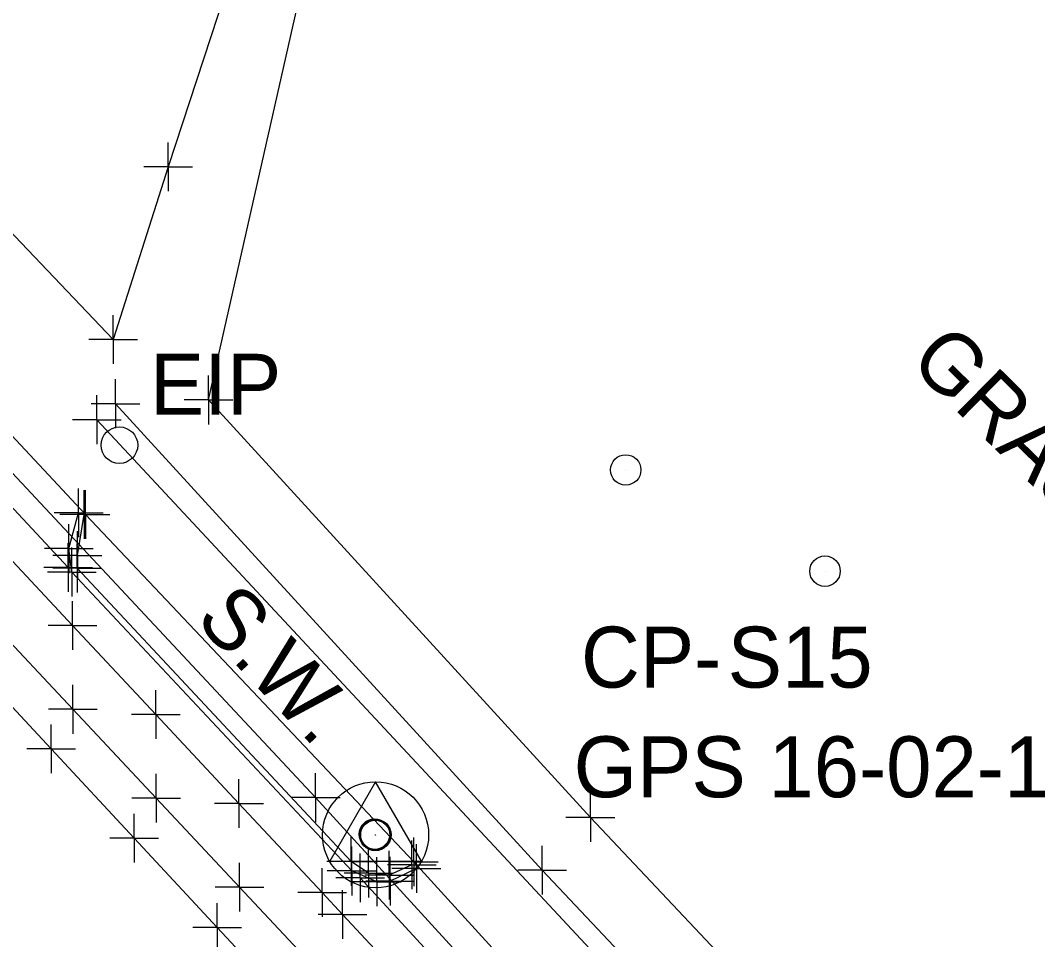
# Model space of a CAD drawing. Extents: x 0 to 1944463, y 0 to 420651.
# Drawn here: x 1943638.6 to 1943722, y 417032.9 to 417108.3 of the extents above; entities that cross this region are included whole.
import ezdxf

# ---------------------------------------------------------------- set-up
doc = ezdxf.new("R2010")
doc.units = 0
for name, color, linetype in [('SUR - CTRL - Points - Numbers', 7, 'Continuous'), ('SUR - CTRL - Points Text', 7, 'Continuous'), ('SUR - DTM - Breaklines', 7, 'Continuous'), ('SUR - DTM - Breaklines - Points - Locators', 7, 'Continuous'), ('SUR - DTM - Spot Points - Locators', 7, 'Continuous'), ('SUR - PROPERTY - Property Lines', 7, 'Continuous'), ('SUR - PROPERTY - Property Markers', 7, 'Continuous'), ('SUR - PROPERTY - ROW Lines', 7, 'Continuous'), ('SUR - TR-CTRL - Pavement Marking', 7, 'Continuous'), ('SUR - TR-CTRL - Pavement Marking - Points - Locators', 7, 'Continuous'), ('SUR - TRAN - Features', 7, 'Continuous'), ('SUR - TRAN - Features - Points - Locators', 7, 'Continuous'), ('SUR - TRAN - Features Text', 7, 'Continuous'), ('SUR - TRAN - Roads', 7, 'Continuous'), ('SUR - UTL - Water', 7, 'Continuous'), ('SUR - UTL - Water - Points - Locators', 7, 'Continuous'), ('SUR - UTL - Water Text', 7, 'Continuous'), ('SUR - VEG - Features Text', 7, 'Continuous'), ('TopoDOT_Transients', 7, 'Continuous')]:
    doc.layers.add(name, color=color, linetype=linetype)

msp = doc.modelspace()

# ---------------------------------------------------------------- linework, layer by layer
at = {"layer": 'SUR - DTM - Breaklines'}
for points in [[(1943783.807, 417052.199), (1943780.542, 417004.601), (1943779.213, 416989.031), (1943776.981, 416981.358), (1943762.371, 416972.888), (1943751.859, 416974.896), (1943741.512, 416982.766), (1943718.161, 417008.084), (1943685.342, 417042.903), (1943654.02, 417077.164), (1943664.758, 417124.782), (1943668.661, 417143.414)], [(1943733.578, 416981.529), (1943714.058, 417003.915), (1943681.394, 417038.588), (1943646.389, 417076.862)], [(1943670.69, 417039.025), (1943668.832, 417038.166), (1943667.154, 417038.334), (1943665.717, 417039.279), (1943643.234, 417063.364), (1943643.254, 417064.4), (1943643.818, 417067.761)], [(1943683.48, 417019.426), (1943666.457, 417037.948)]]:
    msp.add_lwpolyline(points, dxfattribs=at)
at = {"layer": 'SUR - DTM - Breaklines - Points - Locators'}
for p, q in [((1943646.389, 417076.862), (1943646.389, 417078.862)), ((1943654.02, 417077.164), (1943654.02, 417079.164)), ((1943646.389, 417076.862), (1943644.389, 417076.862)), ((1943646.389, 417076.862), (1943648.389, 417076.862)), ((1943646.389, 417076.862), (1943646.389, 417074.862)), ((1943654.02, 417077.164), (1943652.02, 417077.164)), ((1943654.02, 417077.164), (1943656.02, 417077.164)), ((1943654.02, 417077.164), (1943654.02, 417075.164)), ((1943643.818, 417067.761), (1943643.818, 417069.761)), ((1943643.818, 417067.761), (1943641.818, 417067.761)), ((1943643.818, 417067.761), (1943645.818, 417067.761)), ((1943643.818, 417067.761), (1943643.818, 417065.761)), ((1943643.254, 417064.4), (1943643.254, 417066.4)), ((1943643.234, 417063.364), (1943643.234, 417065.364)), ((1943643.254, 417064.4), (1943641.254, 417064.4)), ((1943643.254, 417064.4), (1943645.254, 417064.4)), ((1943643.254, 417064.4), (1943643.254, 417062.4)), ((1943643.234, 417063.364), (1943641.234, 417063.364)), ((1943643.234, 417063.364), (1943645.234, 417063.364)), ((1943643.234, 417063.364), (1943643.234, 417061.364)), ((1943685.342, 417042.903), (1943685.342, 417044.903)), ((1943685.342, 417042.903), (1943683.342, 417042.903)), ((1943685.342, 417042.903), (1943687.342, 417042.903)), ((1943685.342, 417042.903), (1943685.342, 417040.903)), ((1943665.717, 417039.279), (1943665.717, 417041.279)), ((1943670.69, 417039.025), (1943670.69, 417041.025)), ((1943667.154, 417038.334), (1943667.154, 417040.334)), ((1943668.832, 417038.166), (1943668.832, 417040.166)), ((1943681.394, 417038.588), (1943681.394, 417040.588)), ((1943665.717, 417039.279), (1943663.717, 417039.279)), ((1943665.717, 417039.279), (1943667.717, 417039.279)), ((1943665.717, 417039.279), (1943665.717, 417037.279)), ((1943666.457, 417037.948), (1943666.457, 417039.948)), ((1943670.69, 417039.025), (1943668.69, 417039.025)), ((1943670.69, 417039.025), (1943672.69, 417039.025)), ((1943670.69, 417039.025), (1943670.69, 417037.025)), ((1943681.394, 417038.588), (1943679.394, 417038.588)), ((1943681.394, 417038.588), (1943683.394, 417038.588)), ((1943681.394, 417038.588), (1943681.394, 417036.588)), ((1943666.457, 417037.948), (1943664.457, 417037.948)), ((1943667.154, 417038.334), (1943665.154, 417038.334)), ((1943666.457, 417037.948), (1943668.457, 417037.948)), ((1943666.457, 417037.948), (1943666.457, 417035.948)), ((1943668.832, 417038.166), (1943666.832, 417038.166)), ((1943667.154, 417038.334), (1943669.154, 417038.334)), ((1943667.154, 417038.334), (1943667.154, 417036.334)), ((1943668.832, 417038.166), (1943670.832, 417038.166)), ((1943668.832, 417038.166), (1943668.832, 417036.166))]:
    msp.add_line(p, q, dxfattribs=at)
at = {"layer": 'SUR - DTM - Spot Points - Locators'}
for p, q in [((1943688.254, 417071.412), (1943688.254, 417071.412)), ((1943704.603, 417063.108), (1943704.603, 417063.108))]:
    msp.add_line(p, q, dxfattribs=at)
for centre in [(1943688.243, 417071.422), (1943704.592, 417063.118)]:
    msp.add_circle(centre, 1.25, dxfattribs=at)
at = {"layer": 'SUR - PROPERTY - Property Lines'}
for p, q in [((1943642.86, 417058.655), (1943642.86, 417060.655)), ((1943642.86, 417058.655), (1943640.86, 417058.655)), ((1943642.86, 417058.655), (1943644.86, 417058.655)), ((1943642.86, 417058.655), (1943642.86, 417056.655)), ((1943649.687, 417051.348), (1943649.687, 417053.348)), ((1943649.687, 417051.348), (1943647.687, 417051.348)), ((1943649.687, 417051.348), (1943651.687, 417051.348)), ((1943649.687, 417051.348), (1943649.687, 417049.348)), ((1943656.515, 417044.042), (1943656.515, 417046.042)), ((1943656.515, 417044.042), (1943654.515, 417044.042)), ((1943656.515, 417044.042), (1943658.515, 417044.042)), ((1943656.515, 417044.042), (1943656.515, 417042.042)), ((1943663.342, 417036.735), (1943663.342, 417038.735)), ((1943665.012, 417034.948), (1943665.012, 417036.948)), ((1943663.342, 417036.735), (1943661.342, 417036.735)), ((1943663.342, 417036.735), (1943665.342, 417036.735)), ((1943663.342, 417036.735), (1943663.342, 417034.735)), ((1943665.012, 417034.948), (1943663.012, 417034.948)), ((1943665.012, 417034.948), (1943667.012, 417034.948)), ((1943665.012, 417034.948), (1943665.012, 417032.948))]:
    msp.add_line(p, q, dxfattribs=at)
at = {"layer": 'SUR - PROPERTY - Property Markers'}
msp.add_circle((1943646.708, 417073.456), 1.5, dxfattribs=at)
at = {"layer": 'SUR - PROPERTY - ROW Lines'}
for p, q in [((1943667.644, 417041.522), (1943667.644, 417041.522)), ((1943667.663, 417041.437), (1943667.663, 417041.437)), ((1943667.664, 417041.484), (1943667.664, 417041.484)), ((1943667.665, 417041.462), (1943667.665, 417041.462)), ((1943667.668, 417041.477), (1943667.668, 417041.477)), ((1943667.669, 417041.488), (1943667.669, 417041.488)), ((1943667.671, 417041.463), (1943667.671, 417041.463)), ((1943667.678, 417041.51), (1943667.678, 417041.51)), ((1943667.68, 417041.437), (1943667.68, 417041.437)), ((1943667.699, 417041.466), (1943667.699, 417041.466)), ((1943667.702, 417041.439), (1943667.702, 417041.439)), ((1943667.703, 417041.473), (1943667.703, 417041.473)), ((1943667.704, 417041.421), (1943667.704, 417041.421)), ((1943667.705, 417041.485), (1943667.705, 417041.485)), ((1943667.706, 417041.418), (1943667.706, 417041.418)), ((1943667.708, 417041.451), (1943667.708, 417041.451)), ((1943667.709, 417041.479), (1943667.709, 417041.479)), ((1943667.712, 417041.474), (1943667.712, 417041.474)), ((1943667.713, 417041.446), (1943667.713, 417041.446)), ((1943667.717, 417041.449), (1943667.717, 417041.449)), ((1943667.72, 417041.432), (1943667.72, 417041.432)), ((1943667.723, 417041.439), (1943667.723, 417041.439)), ((1943667.725, 417041.493), (1943667.725, 417041.493)), ((1943667.73, 417041.497), (1943667.73, 417041.497)), ((1943667.731, 417041.428), (1943667.731, 417041.428)), ((1943667.738, 417041.439), (1943667.738, 417041.439)), ((1943667.739, 417041.502), (1943667.739, 417041.502)), ((1943667.76, 417041.463), (1943667.76, 417041.463))]:
    msp.add_line(p, q, dxfattribs=at)
for centre in [(1943667.633, 417041.533), (1943667.652, 417041.448), (1943667.653, 417041.495), (1943667.655, 417041.472), (1943667.657, 417041.487), (1943667.658, 417041.498), (1943667.66, 417041.473), (1943667.667, 417041.521), (1943667.669, 417041.448), (1943667.688, 417041.477), (1943667.691, 417041.449), (1943667.693, 417041.484), (1943667.694, 417041.495), (1943667.693, 417041.432), (1943667.696, 417041.429), (1943667.697, 417041.462), (1943667.699, 417041.489), (1943667.701, 417041.484), (1943667.702, 417041.457), (1943667.707, 417041.459), (1943667.71, 417041.443), (1943667.712, 417041.45), (1943667.714, 417041.504), (1943667.719, 417041.508), (1943667.72, 417041.439), (1943667.727, 417041.45), (1943667.728, 417041.513), (1943667.749, 417041.473)]:
    msp.add_circle(centre, 1.25, dxfattribs=at)
at = {"layer": 'SUR - TR-CTRL - Pavement Marking'}
msp.add_lwpolyline([(1943581.298, 417112.609), (1943588.124, 417105.301), (1943594.95, 417097.993), (1943601.776, 417090.685), (1943608.602, 417083.377), (1943615.428, 417076.07), (1943622.255, 417068.762), (1943627.48, 417063.167), (1943634.292, 417055.846), (1943641.104, 417048.525), (1943647.916, 417041.204), (1943654.727, 417033.882), (1943661.539, 417026.561), (1943668.351, 417019.24), (1943675.163, 417011.919), (1943681.975, 417004.598), (1943688.786, 416997.277), (1943695.598, 416989.955), (1943702.41, 416982.634), (1943709.222, 416975.313), (1943716.033, 416967.992), (1943716.328, 416967.675)], dxfattribs=at)
at = {"layer": 'SUR - TR-CTRL - Pavement Marking - Points - Locators'}
for p, q in [((1943641.104, 417048.525), (1943641.104, 417050.525)), ((1943641.104, 417048.525), (1943639.104, 417048.525)), ((1943641.104, 417048.525), (1943643.104, 417048.525)), ((1943641.104, 417048.525), (1943641.104, 417046.525)), ((1943647.916, 417041.204), (1943647.916, 417043.204)), ((1943647.916, 417041.204), (1943645.916, 417041.204)), ((1943647.916, 417041.204), (1943649.916, 417041.204)), ((1943647.916, 417041.204), (1943647.916, 417039.204)), ((1943654.727, 417033.882), (1943654.727, 417035.882)), ((1943654.727, 417033.882), (1943652.727, 417033.882)), ((1943654.727, 417033.882), (1943656.727, 417033.882)), ((1943654.727, 417033.882), (1943654.727, 417031.882))]:
    msp.add_line(p, q, dxfattribs=at)
at = {"layer": 'SUR - TRAN - Features'}
for p, q in [((1943626.355, 417086.597), (1943643.925, 417067.757)), ((1943670.848, 417039.258), (1943685.046, 417023.729))]:
    msp.add_line(p, q, dxfattribs=at)
for points in [[(1943675.686, 417174.052), (1943662.302, 417131.665), (1943650.711, 417096.292), (1943646.198, 417082.119), (1943613.312, 417116.676)], [(1943587.024, 417111.249), (1943593.873, 417103.962), (1943600.721, 417096.675), (1943607.569, 417089.388), (1943614.417, 417082.101), (1943621.266, 417074.814), (1943628.114, 417067.527), (1943634.962, 417060.24), (1943636.052, 417059.081), (1943642.884, 417051.779), (1943649.716, 417044.477), (1943656.548, 417037.174), (1943663.381, 417029.872), (1943670.213, 417022.57), (1943677.045, 417015.268), (1943683.877, 417007.966), (1943690.71, 417000.664), (1943697.09, 416993.845), (1943703.922, 416986.543), (1943710.755, 416979.241), (1943717.587, 416971.939), (1943719.511, 416969.883)], [(1943642.497, 417063.413), (1943623.163, 417084.153)], [(1943738.63, 416975.053), (1943710.045, 417005.565), (1943644.857, 417075.549)], [(1943671.068, 417038.711), (1943668.914, 417037.685), (1943667.817, 417037.632), (1943665.763, 417038.512), (1943642.793, 417063.045), (1943642.558, 417064.965), (1943643.362, 417067.907)], [(1943670.848, 417039.258), (1943643.925, 417067.757)]]:
    msp.add_lwpolyline(points, dxfattribs=at)
at = {"layer": 'SUR - TRAN - Features - Points - Locators'}
for p, q in [((1943650.711, 417096.292), (1943650.711, 417098.292)), ((1943650.711, 417096.292), (1943648.711, 417096.292)), ((1943650.711, 417096.292), (1943652.711, 417096.292)), ((1943650.711, 417096.292), (1943650.711, 417094.292)), ((1943646.198, 417082.119), (1943646.198, 417084.119)), ((1943646.198, 417082.119), (1943644.198, 417082.119)), ((1943646.198, 417082.119), (1943648.198, 417082.119)), ((1943646.198, 417082.119), (1943646.198, 417080.119)), ((1943644.857, 417075.549), (1943644.857, 417077.549)), ((1943644.857, 417075.549), (1943642.857, 417075.549)), ((1943644.857, 417075.549), (1943646.857, 417075.549)), ((1943644.857, 417075.549), (1943644.857, 417073.549)), ((1943643.362, 417067.907), (1943643.362, 417069.907)), ((1943643.925, 417067.757), (1943643.925, 417069.757)), ((1943643.362, 417067.907), (1943641.362, 417067.907)), ((1943643.925, 417067.757), (1943641.925, 417067.757)), ((1943643.362, 417067.907), (1943645.362, 417067.907)), ((1943643.362, 417067.907), (1943643.362, 417065.907)), ((1943643.925, 417067.757), (1943645.925, 417067.757)), ((1943643.925, 417067.757), (1943643.925, 417065.757)), ((1943642.558, 417064.965), (1943642.558, 417066.965)), ((1943642.497, 417063.413), (1943642.497, 417065.413)), ((1943642.558, 417064.965), (1943640.558, 417064.965)), ((1943642.558, 417064.965), (1943644.558, 417064.965)), ((1943642.558, 417064.965), (1943642.558, 417062.965)), ((1943642.793, 417063.045), (1943642.793, 417065.045)), ((1943642.497, 417063.413), (1943640.497, 417063.413)), ((1943642.793, 417063.045), (1943640.793, 417063.045)), ((1943642.497, 417063.413), (1943644.497, 417063.413)), ((1943642.497, 417063.413), (1943642.497, 417061.413)), ((1943642.793, 417063.045), (1943644.793, 417063.045)), ((1943642.793, 417063.045), (1943642.793, 417061.045)), ((1943642.884, 417051.779), (1943642.884, 417053.779)), ((1943642.884, 417051.779), (1943640.884, 417051.779)), ((1943642.884, 417051.779), (1943644.884, 417051.779)), ((1943642.884, 417051.779), (1943642.884, 417049.779)), ((1943649.716, 417044.477), (1943649.716, 417046.477)), ((1943649.716, 417044.477), (1943647.716, 417044.477)), ((1943649.716, 417044.477), (1943651.716, 417044.477)), ((1943649.716, 417044.477), (1943649.716, 417042.477)), ((1943670.848, 417039.258), (1943670.848, 417041.258)), ((1943665.763, 417038.512), (1943665.763, 417040.512)), ((1943671.068, 417038.711), (1943671.068, 417040.711)), ((1943667.817, 417037.632), (1943667.817, 417039.632)), ((1943668.914, 417037.685), (1943668.914, 417039.685)), ((1943656.548, 417037.174), (1943656.548, 417039.174)), ((1943665.763, 417038.512), (1943663.763, 417038.512)), ((1943665.763, 417038.512), (1943667.763, 417038.512)), ((1943665.763, 417038.512), (1943665.763, 417036.512)), ((1943670.848, 417039.258), (1943668.848, 417039.258)), ((1943671.068, 417038.711), (1943669.068, 417038.711)), ((1943670.848, 417039.258), (1943672.848, 417039.258)), ((1943670.848, 417039.258), (1943670.848, 417037.258)), ((1943671.068, 417038.711), (1943673.068, 417038.711)), ((1943671.068, 417038.711), (1943671.068, 417036.711)), ((1943667.817, 417037.632), (1943665.817, 417037.632)), ((1943668.914, 417037.685), (1943666.914, 417037.685)), ((1943667.817, 417037.632), (1943669.817, 417037.632)), ((1943667.817, 417037.632), (1943667.817, 417035.632)), ((1943668.914, 417037.685), (1943670.914, 417037.685)), ((1943668.914, 417037.685), (1943668.914, 417035.685)), ((1943656.548, 417037.174), (1943654.548, 417037.174)), ((1943656.548, 417037.174), (1943658.548, 417037.174)), ((1943656.548, 417037.174), (1943656.548, 417035.174))]:
    msp.add_line(p, q, dxfattribs=at)
at = {"layer": 'SUR - TRAN - Roads'}
msp.add_lwpolyline([(1943595.376, 417109.47), (1943602.203, 417102.163), (1943609.031, 417094.857), (1943615.858, 417087.55), (1943622.377, 417080.574), (1943629.205, 417073.268), (1943636.032, 417065.961), (1943642.86, 417058.655), (1943649.687, 417051.348), (1943656.515, 417044.042), (1943663.342, 417036.735), (1943665.012, 417034.948), (1943671.818, 417027.622), (1943678.624, 417020.296), (1943685.43, 417012.969), (1943692.236, 417005.643), (1943699.042, 416998.316), (1943705.848, 416990.99), (1943712.395, 416983.943), (1943719.275, 416976.686), (1943726.155, 416969.429)], dxfattribs=at)
at = {"layer": 'SUR - UTL - Water'}
msp.add_lwpolyline([(1943736.135, 416965.92), (1943698.624, 417005.311), (1943662.806, 417044.529), (1943623.489, 417086.598), (1943587.47, 417125.24), (1943551.365, 417163.713), (1943514.775, 417202.787), (1943477.504, 417242.514), (1943442.359, 417279.468), (1943414.803, 417309.892), (1943402.764, 417322.345)], dxfattribs=at)
at = {"layer": 'SUR - UTL - Water - Points - Locators'}
for q in [(1943662.806, 417046.529), (1943660.806, 417044.529), (1943664.806, 417044.529), (1943662.806, 417042.529)]:
    msp.add_line((1943662.806, 417044.529), q, dxfattribs=at)
at = {"layer": 'SUR - UTL - Water Text'}
msp.add_open_spline([(1943870.249, 417045.628), (1943772.694, 417014.048), (1943749.453, 417069.458), (1943703.356, 417000.309)], degree=2, dxfattribs=at)
at = {"layer": 'TopoDOT_Transients'}
for p, q in [((1943667.724, 417045.83), (1943663.957, 417039.306)), ((1943671.492, 417039.306), (1943667.724, 417045.83)), ((1943667.724, 417041.48), (1943667.724, 417041.48)), ((1943663.957, 417039.306), (1943671.492, 417039.306))]:
    msp.add_line(p, q, dxfattribs=at)
msp.add_circle((1943667.724, 417041.48), 4.35, dxfattribs=at)

# ---------------------------------------------------------------- texts
at = {"layer": 'SUR - CTRL - Points - Numbers'}
for s, p in [('CP-', (1943684.572, 417053.562)), ('S15', (1943696.604, 417053.562))]:
    msp.add_text(s, height=5, dxfattribs=at).set_placement(p)
at = {"layer": 'SUR - CTRL - Points Text'}
msp.add_text('GPS 16-02-15', height=4.99999, dxfattribs=at).set_placement((1943683.972, 417044.562))
at = {"layer": 'SUR - PROPERTY - Property Markers'}
msp.add_text('EIP', height=5, dxfattribs=at).set_placement((1943649.208, 417075.955))
at = {"layer": 'SUR - TRAN - Features Text'}
msp.add_text('S.W.', height=5, rotation=313.37271, dxfattribs=at).set_placement((1943652.803, 417059.073))
at = {"layer": 'SUR - VEG - Features Text'}
msp.add_text('GRASS', height=5, rotation=315.48092, dxfattribs=at).set_placement((1943711.356, 417080.188))

doc.saveas('drawing.dxf')
